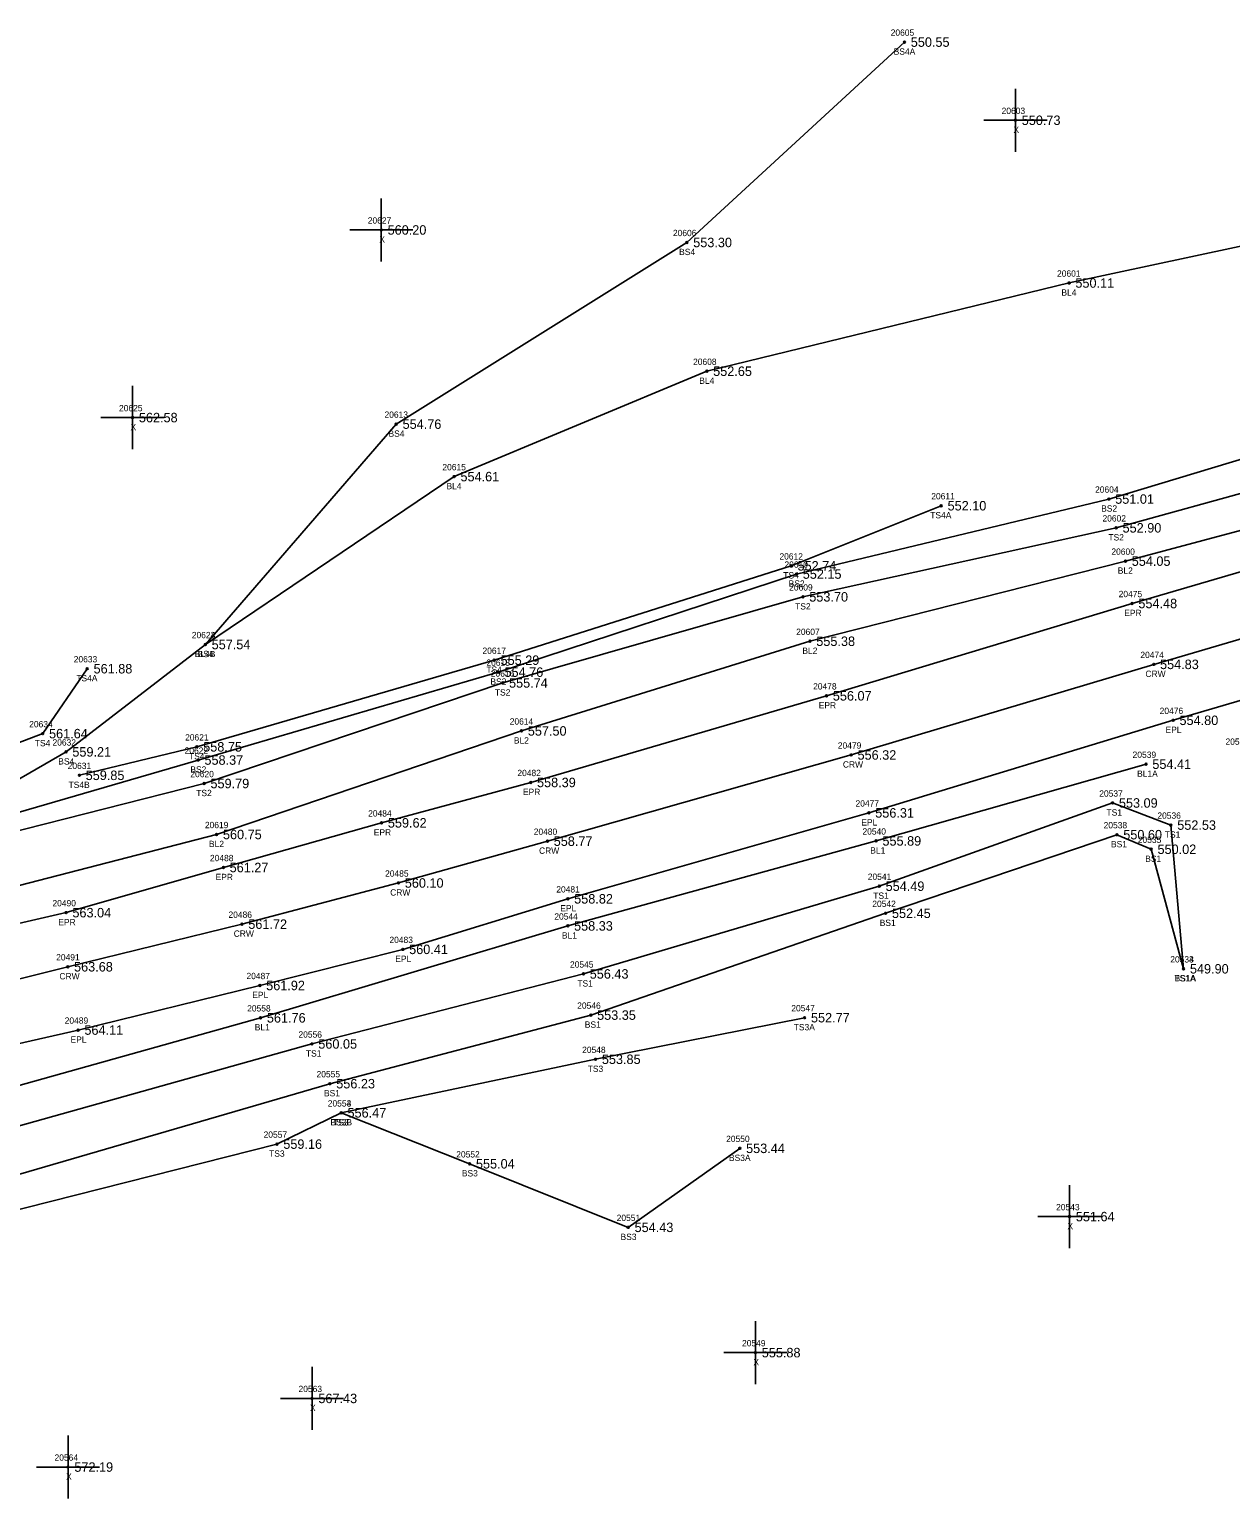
# Model space of a CAD drawing. Extents: x 1540443 to 1541844, y 887157 to 888162.
# Drawn here: x 1540777.9 to 1540968, y 887491.4 to 887724 of the extents above; entities that cross this region are included whole.
import ezdxf

# ---------------------------------------------------------------- set-up
doc = ezdxf.new("R2010")
doc.units = 0
for name, color, linetype in [('RD_DTM_BkLn1', 7, 'Continuous'), ('RD_DTM_BkLn2', 7, 'Continuous'), ('RD_DTM_BkLn_txCode', 7, 'Continuous'), ('RD_EX_Misc', 7, 'Continuous'), ('RD_EX_Misc_txCode', 7, 'Continuous'), ('RD_EX_Road', 7, 'Continuous'), ('RD_EX_Road_txCode', 7, 'Continuous'), ('RD_EX_TX_Misc_ELEV', 7, 'Continuous'), ('RD_EX_TX_Road_ELEV', 7, 'Continuous'), ('RD_HC_Survey_ELEV', 7, 'Continuous'), ('RD_HC_Survey_txCode', 7, 'Continuous'), ('RD_SMD_Locator', 7, 'Continuous')]:
    doc.layers.add(name, color=color, linetype=linetype)

msp = doc.modelspace()

# ---------------------------------------------------------------- linework, layer by layer
at = {"layer": 'RD_DTM_BkLn1'}
for points in [[(1541018.68, 887706.52), (1540988.63, 887693.75), (1540942.45, 887683.87), (1540885.12, 887669.9), (1540845.12, 887653.21), (1540805.74, 887626.62)], [(1541121.11, 887687.12), (1541102.24, 887681.39), (1541047.23, 887667.07), (1540999.54, 887652.68), (1540951.37, 887639.83), (1540901.44, 887627.14), (1540855.78, 887612.94), (1540807.53, 887596.54), (1540760.49, 887584.4), (1540713.89, 887573.7)], [(1541126.44, 887673.83), (1541099.94, 887665.81), (1541052.06, 887651.29), (1541003.93, 887637.63), (1540955.85, 887623.48), (1540907.97, 887609.13), (1540859.88, 887595.48), (1540836.31, 887588.86), (1540811.54, 887582.34), (1540783.96, 887575.59), (1540763.17, 887570.39), (1540738.15, 887565.52), (1540714.18, 887561.19), (1540687.63, 887557.81), (1540664.59, 887555.61), (1540640.72, 887554.4), (1540614.88, 887554.02), (1540589.98, 887554.69), (1540565.01, 887555.56), (1540543.6, 887557.4), (1540515.55, 887560.7), (1540490.9, 887564.25), (1540466.38, 887568.75)], [(1540954.63, 887607.67), (1540911.91, 887595.52), (1540863.1, 887582.06), (1540814.48, 887567.51), (1540766.41, 887554.06), (1540717.46, 887541.1), (1540667.62, 887534.76)]]:
    msp.add_lwpolyline(points, dxfattribs=at)
at = {"layer": 'RD_DTM_BkLn2'}
for points in [[(1540916.4, 887722.02), (1540881.96, 887690.29), (1540835.96, 887661.52), (1540805.74, 887626.62), (1540783.69, 887609.62), (1540757.89, 887594.74)], [(1541125.73, 887711), (1541094.52, 887702.99), (1541086.54, 887695.93), (1541048.87, 887683.66), (1540995.75, 887663.85), (1540948.75, 887649.66), (1540899.3, 887637.78), (1540852.09, 887622.25), (1540804.6, 887608.33), (1540757.89, 887594.74), (1540710.97, 887581.88), (1540663.03, 887573.83), (1540613.52, 887571.27), (1540565.55, 887571.13), (1540516.75, 887576.29), (1540467.77, 887583.94)], [(1541121.11, 887687.12), (1541116.34, 887691.41), (1541100.71, 887685.78), (1541045.17, 887674.13), (1540997.29, 887658.19), (1540949.92, 887645.1), (1540900.33, 887634.17), (1540852.81, 887620.54), (1540805.55, 887604.61), (1540758.2, 887592.6), (1540711.88, 887580.02), (1540663.85, 887571.28), (1540613.62, 887569.93), (1540565.66, 887569.42), (1540516.87, 887574.64), (1540467.8, 887581.76)], [(1540922.22, 887648.6), (1540898.47, 887639.08), (1540851.47, 887624.14), (1540804.4, 887610.42), (1540785.8, 887605.91)], [(1540787.05, 887622.79), (1540780, 887612.51), (1540763.75, 887606.38), (1540712.71, 887590.91), (1540681.48, 887584.18), (1540666, 887596.16), (1540654.52, 887623.68)], [(1540960.58, 887575.27), (1540958.57, 887598.03), (1540949.34, 887601.53), (1540912.42, 887588.35), (1540865.58, 887574.46), (1540822.62, 887563.37), (1540767.41, 887547.91), (1540718.66, 887535.26), (1540668.13, 887523.76), (1540649.26, 887523.14), (1540607.24, 887534.95), (1540564.64, 887539.95), (1540513.61, 887544.12), (1540463.72, 887552.73)], [(1540960.58, 887575.27), (1540955.45, 887594.2), (1540950.03, 887596.51), (1540913.42, 887584.06), (1540866.75, 887567.94), (1540825.46, 887557.08), (1540769.44, 887540.76), (1540737.8, 887532.98), (1540709.87, 887528.84), (1540668.36, 887521.72), (1540649.18, 887520.9), (1540606.9, 887532.51), (1540564.07, 887536.98), (1540513.03, 887541.52), (1540462.71, 887549.66)], [(1540900.6, 887567.53), (1540867.5, 887560.94), (1540827.24, 887552.46), (1540817.08, 887547.51), (1540769.29, 887535.4), (1540757.62, 887529.33), (1540742.46, 887495.55)], [(1540890.33, 887546.84), (1540872.68, 887534.33), (1540847.57, 887544.39), (1540827.24, 887552.46)]]:
    msp.add_lwpolyline(points, dxfattribs=at)
at = {"layer": 'RD_EX_Misc'}
for p, q in [((1540933.96, 887704.64), (1540933.96, 887714.64)), ((1540928.96, 887709.64), (1540938.96, 887709.64)), ((1540833.59, 887687.27), (1540833.59, 887697.27)), ((1540828.59, 887692.27), (1540838.59, 887692.27)), ((1540794.22, 887657.56), (1540794.22, 887667.56)), ((1540789.22, 887662.56), (1540799.22, 887662.56)), ((1540942.52, 887531.03), (1540942.52, 887541.03)), ((1540937.52, 887536.03), (1540947.52, 887536.03)), ((1540892.81, 887509.49), (1540892.81, 887519.49)), ((1540887.81, 887514.49), (1540897.81, 887514.49)), ((1540822.63, 887502.24), (1540822.63, 887512.24)), ((1540817.63, 887507.24), (1540827.63, 887507.24)), ((1540784.01, 887491.37), (1540784.01, 887501.37)), ((1540779.01, 887496.37), (1540789.01, 887496.37))]:
    msp.add_line(p, q, dxfattribs=at)
at = {"layer": 'RD_EX_Road'}
for points in [[(1541123.73, 887682.83), (1541097.11, 887675.72), (1541048.24, 887661.15), (1541001.64, 887647.51), (1540952.42, 887633.12), (1540904.06, 887618.5), (1540857.24, 887604.78), (1540833.63, 887598.38), (1540808.59, 887591.31), (1540783.7, 887584.16), (1540761.05, 887578.97), (1540736.42, 887574.18), (1540712.73, 887570.56), (1540686.82, 887567.49), (1540663.33, 887565.48), (1540639.94, 887564.35), (1540615, 887563.38), (1540590.61, 887563.9), (1540565.81, 887565.05), (1540541.4, 887567.22), (1540516.92, 887569.69), (1540492.5, 887573.72), (1540467.49, 887577.97)], [(1541128.99, 887664.81), (1541102.04, 887656.79), (1541055.37, 887642.78), (1541004.6, 887628.06), (1540958.93, 887614.62), (1540910.77, 887599.96), (1540863.12, 887586.35), (1540837, 887578.35), (1540814.37, 887572.63), (1540785.6, 887565.57), (1540765.56, 887561), (1540743.15, 887555.32), (1540714.84, 887552.19), (1540688.66, 887548.15), (1540665.15, 887545.04), (1540640.91, 887544.2), (1540614.99, 887544.1), (1540590.77, 887544.52), (1540565.35, 887545.64), (1540542.9, 887547.56), (1540513.68, 887550.75), (1540490.5, 887554.02), (1540464.65, 887559.04)]]:
    msp.add_lwpolyline(points, dxfattribs=at)
at = {"layer": 'RD_SMD_Locator'}
for centre in [(1540916.4, 887722.02), (1540933.96, 887709.64), (1540833.59, 887692.27), (1540881.96, 887690.29), (1540942.45, 887683.87), (1540885.12, 887669.9), (1540794.22, 887662.56), (1540835.96, 887661.52), (1540845.12, 887653.21), (1540922.22, 887648.6), (1540948.75, 887649.66), (1540949.92, 887645.1), (1540898.47, 887639.08), (1540951.37, 887639.83), (1540899.3, 887637.78), (1540900.33, 887634.17), (1540952.42, 887633.12), (1540901.44, 887627.14), (1540805.74, 887626.62), (1540805.74, 887626.62), (1540787.05, 887622.79), (1540851.47, 887624.14), (1540852.09, 887622.25), (1540955.85, 887623.48), (1540852.81, 887620.54), (1540904.06, 887618.5), (1540855.78, 887612.94), (1540958.93, 887614.62), (1540780, 887612.51), (1540783.69, 887609.62), (1540804.4, 887610.42), (1540804.6, 887608.33), (1540907.97, 887609.13), (1540954.63, 887607.67), (1540785.8, 887605.91), (1540805.55, 887604.61), (1540857.24, 887604.78), (1540949.34, 887601.53), (1540910.77, 887599.96), (1540833.63, 887598.38), (1540958.57, 887598.03), (1540807.53, 887596.54), (1540859.88, 887595.48), (1540911.91, 887595.52), (1540950.03, 887596.51), (1540955.45, 887594.2), (1540808.59, 887591.31), (1540836.31, 887588.86), (1540912.42, 887588.35), (1540863.12, 887586.35), (1540783.7, 887584.16), (1540913.42, 887584.06), (1540811.54, 887582.34), (1540863.1, 887582.06), (1540837, 887578.35), (1540783.96, 887575.59), (1540865.58, 887574.46), (1540960.58, 887575.27), (1540960.58, 887575.27), (1540814.37, 887572.63), (1540814.48, 887567.51), (1540866.75, 887567.94), (1540900.6, 887567.53), (1540785.6, 887565.57), (1540822.62, 887563.37), (1540867.5, 887560.94), (1540825.46, 887557.08), (1540827.24, 887552.46), (1540827.24, 887552.46), (1540817.08, 887547.51), (1540890.33, 887546.84), (1540847.57, 887544.39), (1540872.68, 887534.33), (1540942.52, 887536.03), (1540892.81, 887514.49), (1540822.63, 887507.24), (1540784.01, 887496.37)]:
    msp.add_circle(centre, 0.15, dxfattribs=at)

# ---------------------------------------------------------------- texts
at = {"layer": 'RD_DTM_BkLn_txCode'}
for s, p in [('20605', (1540914.22, 887723.02)), ('BS4A', (1540914.69, 887720.02)), ('20606', (1540879.75, 887691.29)), ('BS4', (1540880.73, 887688.29)), ('20601', (1540940.55, 887684.87)), ('BL4', (1540941.24, 887681.87)), ('20608', (1540882.94, 887670.9)), ('BL4', (1540883.92, 887667.9)), ('20613', (1540834.1, 887662.52)), ('BS4', (1540834.73, 887659.52)), ('20615', (1540843.26, 887654.21)), ('BL4', (1540843.91, 887651.21)), ('20611', (1540920.64, 887649.6)), ('20604', (1540946.57, 887650.66)), ('BS2', (1540947.53, 887647.66)), ('TS4A', (1540920.48, 887646.6)), ('20602', (1540947.74, 887646.1)), ('TS2', (1540948.68, 887643.1)), ('20612', (1540896.61, 887640.08)), ('20600', (1540949.15, 887640.83)), ('20610', (1540897.4, 887638.78)), ('BL2', (1540950.16, 887637.83)), ('TS4', (1540897.22, 887637.08)), ('BS2', (1540898.07, 887635.78)), ('20609', (1540898.15, 887635.17)), ('TS2', (1540899.09, 887632.17)), ('20623', (1540803.6, 887627.62)), ('20624', (1540803.6, 887627.62)), ('20607', (1540899.26, 887628.14)), ('20633', (1540784.91, 887623.79)), ('BL4B', (1540804.06, 887624.62)), ('BS4', (1540804.51, 887624.62)), ('20617', (1540849.61, 887625.14)), ('BL2', (1540900.24, 887625.14)), ('TS4', (1540850.22, 887622.14)), ('20618', (1540850.23, 887623.25)), ('20616', (1540850.93, 887621.54)), ('TS4A', (1540785.32, 887620.79)), ('BS2', (1540850.86, 887620.25)), ('TS2', (1540851.57, 887618.54)), ('20634', (1540777.86, 887613.51)), ('20614', (1540853.92, 887613.94)), ('TS4', (1540778.75, 887610.51)), ('20632', (1540781.55, 887610.62)), ('20621', (1540802.54, 887611.42)), ('BL2', (1540854.57, 887610.94)), ('20527', (1540967.21, 887610.74)), ('BS4', (1540782.46, 887607.62)), ('20622', (1540802.46, 887609.33)), ('TS4', (1540803.16, 887608.42)), ('20539', (1540952.51, 887608.67)), ('20631', (1540783.95, 887606.91)), ('20620', (1540803.37, 887605.61)), ('BS2', (1540803.37, 887606.33)), ('BL1A', (1540953.22, 887605.67)), ('TS4B', (1540784.09, 887603.91)), ('TS2', (1540804.3, 887602.61)), ('20537', (1540947.23, 887602.53)), ('TS1', (1540948.38, 887599.53)), ('20536', (1540956.43, 887599.03)), ('20619', (1540805.67, 887597.54)), ('20540', (1540909.75, 887596.52)), ('20538', (1540947.92, 887597.51)), ('TS1', (1540957.61, 887596.03)), ('BL2', (1540806.32, 887594.54)), ('BL1', (1540910.99, 887593.52)), ('BS1', (1540949.09, 887594.51)), ('20535', (1540953.33, 887595.2)), ('BS1', (1540954.5, 887592.2)), ('20541', (1540910.59, 887589.35)), ('20542', (1540911.31, 887585.06)), ('TS1', (1540911.46, 887586.35)), ('20544', (1540860.98, 887583.06)), ('BS1', (1540912.48, 887582.06)), ('BL1', (1540862.18, 887580.06)), ('20545', (1540863.46, 887575.46)), ('20533', (1540958.47, 887576.27)), ('20534', (1540958.47, 887576.27)), ('TS1A', (1540959.13, 887573.27)), ('BS1A', (1540959.15, 887573.27)), ('TS1', (1540864.62, 887572.46)), ('20558', (1540812.36, 887568.51)), ('20546', (1540864.6, 887568.94)), ('20547', (1540898.49, 887568.53)), ('BS1', (1540865.8, 887565.94)), ('TS3A', (1540898.87, 887565.53)), ('BL1', (1540813.56, 887565.51)), ('20556', (1540820.48, 887564.37)), ('TS1', (1540821.66, 887561.37)), ('20548', (1540865.38, 887561.94)), ('TS3', (1540866.26, 887558.94)), ('20555', (1540823.34, 887558.08)), ('BS1', (1540824.52, 887555.08)), ('20553', (1540825.12, 887553.46)), ('20554', (1540825.12, 887553.46)), ('BS3B', (1540825.54, 887550.46)), ('TS3', (1540825.99, 887550.46)), ('20557', (1540814.96, 887548.51)), ('20550', (1540888.17, 887547.84)), ('TS3', (1540815.84, 887545.51)), ('20552', (1540845.45, 887545.39)), ('BS3A', (1540888.62, 887544.84)), ('BS3', (1540846.34, 887542.39)), ('20551', (1540870.85, 887535.33)), ('BS3', (1540871.46, 887532.33))]:
    msp.add_text(s, height=1, dxfattribs=at).set_placement(p)
at = {"layer": 'RD_EX_Misc_txCode'}
for s, p in [('20603', (1540931.78, 887710.64)), ('X', (1540933.65, 887707.64)), ('20627', (1540831.45, 887693.27)), ('X', (1540833.28, 887690.27)), ('20625', (1540792.08, 887663.56)), ('X', (1540793.9, 887660.56)), ('20543', (1540940.4, 887537.03)), ('X', (1540942.2, 887534.03)), ('20549', (1540890.69, 887515.49)), ('X', (1540892.49, 887512.49)), ('20563', (1540820.49, 887508.24)), ('X', (1540822.31, 887505.24)), ('20564', (1540781.87, 887497.37)), ('X', (1540783.7, 887494.37))]:
    msp.add_text(s, height=1, dxfattribs=at).set_placement(p)
at = {"layer": 'RD_EX_Road_txCode'}
for s, p in [('20475', (1540950.3, 887634.12)), ('EPR', (1540951.19, 887631.12)), ('20478', (1540901.94, 887619.5)), ('EPR', (1540902.83, 887616.5)), ('20476', (1540956.79, 887615.62)), ('EPL', (1540957.72, 887612.62)), ('20482', (1540855.13, 887605.78)), ('EPR', (1540856.02, 887602.78)), ('20477', (1540908.65, 887600.96)), ('20484', (1540831.51, 887599.38)), ('EPR', (1540832.4, 887596.38)), ('EPL', (1540909.57, 887597.96)), ('20488', (1540806.47, 887592.31)), ('EPR', (1540807.36, 887589.31)), ('20481', (1540861.29, 887587.35)), ('20490', (1540781.54, 887585.16)), ('EPL', (1540861.92, 887584.35)), ('EPR', (1540782.47, 887582.16)), ('20483', (1540834.88, 887579.35)), ('EPL', (1540835.8, 887576.35)), ('20487', (1540812.25, 887573.63)), ('EPL', (1540813.17, 887570.63)), ('20489', (1540783.48, 887566.57)), ('EPL', (1540784.4, 887563.57))]:
    msp.add_text(s, height=1, dxfattribs=at).set_placement(p)
at = {"layer": 'RD_EX_TX_Misc_ELEV'}
for s, p in [('550.55', (1540917.4, 887721.27)), ('550.73', (1540934.96, 887708.89)), ('560.20', (1540834.59, 887691.52)), ('553.30', (1540882.96, 887689.54)), ('550.11', (1540943.45, 887683.12)), ('552.65', (1540886.12, 887669.15)), ('562.58', (1540795.22, 887661.81)), ('554.76', (1540836.96, 887660.77)), ('554.61', (1540846.12, 887652.46)), ('551.01', (1540949.75, 887648.91)), ('552.10', (1540923.22, 887647.85)), ('552.90', (1540950.92, 887644.35)), ('552.74', (1540899.47, 887638.33)), ('554.05', (1540952.37, 887639.08)), ('552.15', (1540900.3, 887637.03)), ('553.70', (1540901.33, 887633.42)), ('557.54', (1540806.74, 887625.87)), ('557.54', (1540806.74, 887625.87)), ('555.38', (1540902.44, 887626.39)), ('555.29', (1540852.47, 887623.39)), ('561.88', (1540788.05, 887622.04)), ('554.76', (1540853.09, 887621.5)), ('555.74', (1540853.81, 887619.79)), ('561.64', (1540781, 887611.76)), ('557.50', (1540856.78, 887612.19)), ('558.75', (1540805.4, 887609.67)), ('559.21', (1540784.69, 887608.87)), ('558.37', (1540805.6, 887607.58)), ('554.41', (1540955.63, 887606.92)), ('559.85', (1540786.8, 887605.16)), ('559.79', (1540806.55, 887603.86)), ('553.09', (1540950.34, 887600.78)), ('560.75', (1540808.53, 887595.79)), ('550.60', (1540951.03, 887595.76)), ('552.53', (1540959.57, 887597.28)), ('555.89', (1540912.91, 887594.77)), ('550.02', (1540956.45, 887593.45)), ('554.49', (1540913.42, 887587.6)), ('558.33', (1540864.1, 887581.31)), ('552.45', (1540914.42, 887583.31)), ('549.90', (1540961.58, 887574.52)), ('549.90', (1540961.58, 887574.52)), ('556.43', (1540866.58, 887573.71)), ('561.76', (1540815.48, 887566.76)), ('553.35', (1540867.75, 887567.19)), ('552.77', (1540901.6, 887566.78)), ('560.05', (1540823.62, 887562.62)), ('553.85', (1540868.5, 887560.19)), ('556.23', (1540826.46, 887556.33)), ('556.47', (1540828.24, 887551.71)), ('556.47', (1540828.24, 887551.71)), ('559.16', (1540818.08, 887546.76)), ('553.44', (1540891.33, 887546.09)), ('555.04', (1540848.57, 887543.64)), ('551.64', (1540943.52, 887535.28)), ('554.43', (1540873.68, 887533.58)), ('555.88', (1540893.81, 887513.74)), ('567.43', (1540823.63, 887506.49)), ('572.19', (1540785.01, 887495.62))]:
    msp.add_text(s, height=1.5, dxfattribs=at).set_placement(p)
at = {"layer": 'RD_EX_TX_Road_ELEV'}
for s, p in [('554.48', (1540953.42, 887632.37)), ('556.07', (1540905.06, 887617.75)), ('554.80', (1540959.93, 887613.87)), ('558.39', (1540858.24, 887604.03)), ('559.62', (1540834.63, 887597.63)), ('556.31', (1540911.77, 887599.21)), ('561.27', (1540809.59, 887590.56)), ('558.82', (1540864.12, 887585.6)), ('563.04', (1540784.7, 887583.41)), ('560.41', (1540838, 887577.6)), ('561.92', (1540815.37, 887571.88)), ('564.11', (1540786.6, 887564.82))]:
    msp.add_text(s, height=1.5, dxfattribs=at).set_placement(p)
at = {"layer": 'RD_HC_Survey_ELEV'}
for s, p in [('554.83', (1540956.85, 887622.73)), ('556.32', (1540908.97, 887608.38)), ('558.77', (1540860.88, 887594.73)), ('560.10', (1540837.31, 887588.11)), ('561.72', (1540812.54, 887581.59)), ('563.68', (1540784.96, 887574.84))]:
    msp.add_text(s, height=1.5, dxfattribs=at).set_placement(p)
at = {"layer": 'RD_HC_Survey_txCode'}
for s, p in [('20474', (1540953.74, 887624.48)), ('CRW', (1540954.54, 887621.48)), ('20479', (1540905.85, 887610.13)), ('CRW', (1540906.65, 887607.13)), ('20480', (1540857.72, 887596.48)), ('CRW', (1540858.56, 887593.48)), ('20485', (1540834.19, 887589.86)), ('CRW', (1540835, 887586.86)), ('20486', (1540809.4, 887583.34)), ('CRW', (1540810.23, 887580.34)), ('20491', (1540782.13, 887576.59)), ('CRW', (1540782.65, 887573.59))]:
    msp.add_text(s, height=1, dxfattribs=at).set_placement(p)

doc.saveas('drawing.dxf')
